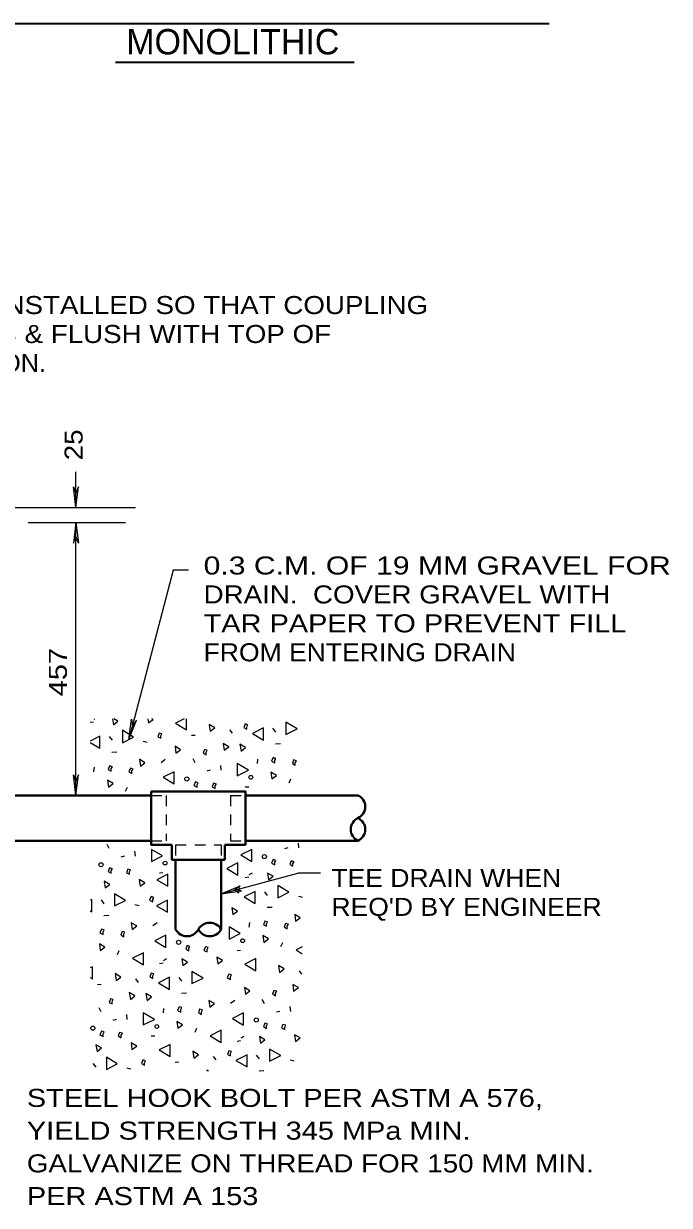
# Model space of a CAD drawing. Extents: x 312583 to 312854, y 144419 to 144597.
# Drawn here: x 312661.67 to 312688.9, y 144471.8 to 144521.63 of the extents above; entities that cross this region are included whole.
import ezdxf
from ezdxf.enums import TextEntityAlignment as Align

# ---------------------------------------------------------------- set-up
doc = ezdxf.new("R2010")
doc.units = 0
doc.header["$LTSCALE"] = 0.3
doc.linetypes.add('SHORT_DASHED', pattern=[2.7, 1.5, -1.2])
doc.layers.add('1', color=7, linetype='Continuous', lineweight=25)
doc.layers.add('2', color=7, linetype='Continuous', lineweight=13)

msp = doc.modelspace()

# ---------------------------------------------------------------- linework, layer by layer
at = {"layer": '1', "lineweight": 40}
for p, q in [((312658.9047, 144489.089), (312667.0467, 144489.089)), ((312671.0333, 144489.089), (312675.7713, 144489.089)), ((312658.9047, 144487.1723), (312667.0467, 144487.1723)), ((312667.9207, 144487.0113), (312667.9207, 144486.375)), ((312670.1593, 144487.0113), (312671.0333, 144487.0113)), ((312670.1593, 144487.0113), (312670.1593, 144486.375)), ((312671.0333, 144487.1723), (312675.7713, 144487.1723)), ((312667.9207, 144486.375), (312670.1593, 144486.375)), ((312668.0817, 144486.375), (312668.0817, 144483.4387)), ((312669.9983, 144486.375), (312669.9983, 144483.4387))]:
    msp.add_line(p, q, dxfattribs=at)
at = {"layer": '1', "linetype": 'SHORT_DASHED'}
for p, q in [((312667.0467, 144489.089), (312667.683, 144489.089)), ((312667.683, 144489.089), (312667.683, 144487.1723)), ((312670.397, 144489.089), (312670.397, 144487.1723)), ((312670.397, 144489.089), (312671.0333, 144489.089)), ((312667.0467, 144487.1723), (312667.683, 144487.1723)), ((312668.0817, 144487.0113), (312669.9983, 144487.0113)), ((312668.0817, 144487.0113), (312668.0817, 144486.375)), ((312669.9983, 144487.0113), (312669.9983, 144486.375)), ((312670.397, 144487.1723), (312671.0333, 144487.1723))]:
    msp.add_line(p, q, dxfattribs=at)
at = {"layer": '1', "lineweight": 40}
for points in [[(312667.0467, 144489.25), (312671.0333, 144489.25), (312671.0333, 144487.0113)], [(312667.0467, 144489.25), (312667.0467, 144487.0113), (312667.9207, 144487.0113)]]:
    msp.add_lwpolyline(points, dxfattribs=at)
for centre, radius, start, end in [((312675.5491, 144488.6118), 0.5279, 294.81419, 65.18581), ((312675.9922, 144487.6534), 0.5279, 114.81419, 245.18581), ((312675.5491, 144487.6534), 0.5279, 294.81419, 65.18581), ((312669.5192, 144483.175), 0.5466, 28.76662, 151.23338), ((312668.5608, 144483.7011), 0.5466, 208.76662, 331.23338), ((312669.5192, 144483.7011), 0.5466, 208.76662, 331.23338)]:
    msp.add_arc(centre, radius, start, end, dxfattribs=at)
at = {"layer": '2', "lineweight": 35}
for p, q in [((312657.2919, 144521.6292), (312683.8367, 144521.6292)), ((312665.5535, 144520.0115), (312675.611, 144520.0115))]:
    msp.add_line(p, q, dxfattribs=at)
at = {"layer": '2'}
for p, q in [((312663.8803, 144501.233), (312663.8803, 144502.7357)), ((312663.773, 144502.0993), (312663.8803, 144501.8233)), ((312663.8803, 144501.233), (312663.773, 144502.0993)), ((312663.9877, 144502.0993), (312663.8803, 144501.8233)), ((312663.8803, 144501.233), (312663.9877, 144502.0993)), ((312651.8743, 144501.233), (312666.395, 144501.233)), ((312661.8717, 144500.589), (312665.9657, 144500.589)), ((312663.8803, 144500.589), (312663.773, 144499.7227)), ((312663.8803, 144489.089), (312663.8803, 144500.589)), ((312663.8803, 144500.589), (312663.9877, 144499.7227)), ((312663.773, 144499.7227), (312663.8803, 144499.9987)), ((312663.9877, 144499.7227), (312663.8803, 144499.9987)), ((312664.486, 144492.171), (312664.624, 144492.194)), ((312664.647, 144492.3013), (312664.6777, 144492.3167)), ((312665.4213, 144492.3167), (312665.4597, 144492.0713)), ((312666.1113, 144491.4427), (312666.2263, 144492.309)), ((312666.1113, 144491.4427), (312666.4333, 144492.2553)), ((312666.2263, 144492.309), (312666.257, 144492.01)), ((312666.4333, 144492.2553), (312666.257, 144492.01)), ((312666.9087, 144492.3167), (312666.9317, 144492.148)), ((312668.5417, 144491.8567), (312668.5417, 144492.3167)), ((312665.2833, 144491.573), (312665.406, 144491.412)), ((312668.7563, 144491.6267), (312668.9097, 144491.6343)), ((312670.3587, 144491.8567), (312670.466, 144491.7187)), ((312672.168, 144491.918), (312672.2907, 144491.757)), ((312664.486, 144491.32), (312664.8923, 144491.0747)), ((312666.7093, 144491.3813), (312666.8857, 144491.3353)), ((312672.2907, 144491.2587), (312672.4977, 144491.274)), ((312665.3983, 144490.9137), (312665.6053, 144490.929)), ((312667.6447, 144490.607), (312667.4683, 144490.469)), ((312668.8023, 144490.6453), (312668.8867, 144490.4767)), ((312671.5317, 144490.4307), (312671.5547, 144490.6223)), ((312664.6393, 144490.0857), (312664.6623, 144490.2773)), ((312669.408, 144490.124), (312669.5537, 144490.1623)), ((312669.9677, 144490.354), (312669.9907, 144490.147)), ((312663.773, 144489.9553), (312663.8803, 144489.6793)), ((312663.8803, 144489.089), (312663.773, 144489.9553)), ((312663.9877, 144489.9553), (312663.8803, 144489.6793)), ((312663.8803, 144489.089), (312663.9877, 144489.9553)), ((312672.927, 144489.7713), (312672.8503, 144489.6027)), ((312666.0347, 144489.4263), (312665.958, 144489.2577)), ((312671.0103, 144489.4493), (312671.1637, 144489.457)), ((312665.1837, 144487.0267), (312665.268, 144486.858)), ((312667.913, 144486.812), (312667.936, 144487.0037)), ((312673.2413, 144487.0803), (312673.2643, 144486.8733)), ((312665.7893, 144486.5053), (312665.935, 144486.5437)), ((312666.349, 144486.7353), (312666.372, 144486.5283)), ((312672.6817, 144486.8503), (312672.8273, 144486.8887)), ((312667.3993, 144485.8307), (312667.545, 144485.8383)), ((312669.9983, 144484.9337), (312673.2337, 144485.8153)), ((312671.018, 144485.6237), (312671.1637, 144485.6543)), ((312671.1867, 144485.754), (312671.317, 144485.823)), ((312674.1843, 144485.8153), (312673.2337, 144485.8153)), ((312669.9983, 144484.9337), (312670.8033, 144485.271)), ((312669.9983, 144484.9337), (312670.8647, 144485.064)), ((312670.8033, 144485.271), (312670.5657, 144485.0947)), ((312670.8647, 144485.064), (312670.5657, 144485.0947)), ((312671.823, 144485.0257), (312671.9457, 144484.8647)), ((312664.9383, 144484.6807), (312665.061, 144484.5197)), ((312673.2567, 144484.834), (312673.4177, 144484.7957)), ((312664.486, 144484.2207), (312664.555, 144484.1823)), ((312665.0533, 144484.029), (312665.2603, 144484.0367)), ((312666.3643, 144484.489), (312666.5407, 144484.4507)), ((312671.9457, 144484.374), (312672.1527, 144484.3817)), ((312667.2997, 144483.7147), (312667.1233, 144483.5843)), ((312671.1867, 144483.5383), (312671.2097, 144483.73)), ((312665.6897, 144482.534), (312665.613, 144482.3653)), ((312670.673, 144482.557), (312670.8187, 144482.5647)), ((312672.582, 144482.879), (312672.5053, 144482.7103)), ((312667.3993, 144482.005), (312667.5527, 144482.0357)), ((312667.5757, 144482.1353), (312667.6983, 144482.212)), ((312673.2873, 144481.6983), (312673.3947, 144481.5527)), ((312664.486, 144481.407), (312664.578, 144481.3533)), ((312664.7927, 144481.1157), (312664.946, 144481.131)), ((312666.395, 144481.3533), (312666.5023, 144481.2077)), ((312668.212, 144481.407), (312668.3347, 144481.2537)), ((312668.327, 144480.7553), (312668.534, 144480.763)), ((312664.8387, 144480.142), (312664.923, 144479.9733)), ((312667.568, 144479.9273), (312667.591, 144480.1113)), ((312670.5733, 144480.441), (312670.397, 144480.3107)), ((312671.7233, 144480.487), (312671.8153, 144480.3183)), ((312672.8963, 144480.1957), (312672.9193, 144479.981)), ((312665.4443, 144479.613), (312665.59, 144479.659)), ((312666.004, 144479.8507), (312666.027, 144479.636)), ((312672.3367, 144479.958), (312672.4823, 144479.9963)), ((312668.9633, 144479.2603), (312668.8867, 144479.0917)), ((312667.0543, 144478.946), (312667.2, 144478.946)), ((312670.673, 144478.7313), (312670.8187, 144478.762)), ((312670.8417, 144478.8693), (312670.972, 144478.9383)), ((312669.6687, 144478.0797), (312669.776, 144477.934)), ((312671.478, 144478.1333), (312671.6007, 144477.98)), ((312664.5933, 144477.7883), (312664.716, 144477.635)), ((312666.027, 144477.5967), (312666.1957, 144477.5583)), ((312668.0663, 144477.842), (312668.2197, 144477.8573)), ((312672.9117, 144477.9417), (312673.0803, 144477.9033)), ((312671.6007, 144477.4817), (312671.8077, 144477.4893))]:
    msp.add_line(p, q, dxfattribs=at)
for points in [[(312668.626, 144498.588), (312667.9743, 144498.588), (312666.1113, 144491.4427)], [(312665.4597, 144492.0713), (312665.6513, 144492.217), (312665.4827, 144492.3167)], [(312666.9317, 144492.148), (312667.131, 144492.2937), (312667.085, 144492.3167)], [(312668.442, 144492.3167), (312668.074, 144492.1403), (312668.5417, 144491.8567)], [(312664.8923, 144491.0747), (312664.8923, 144491.5883), (312664.486, 144491.3813)], [(312664.555, 144484.1823), (312664.555, 144484.696), (312664.486, 144484.6653)], [(312673.4177, 144482.7027), (312673.157, 144482.5723), (312673.4177, 144482.4113)], [(312664.578, 144481.3533), (312664.578, 144481.867), (312664.486, 144481.821)], [(312669.4617, 144477.4663), (312669.4003, 144477.5047), (312669.408, 144477.4663)]]:
    msp.add_lwpolyline(points, dxfattribs=at)
for points in [[(312669.5383, 144491.7953), (312669.73, 144491.941), (312669.4923, 144492.079)], [(312671.087, 144491.987), (312671.133, 144492.0637), (312671.0103, 144492.102), (312670.9567, 144491.9487), (312671.087, 144491.8797)], [(312672.7353, 144492.1787), (312672.7353, 144491.6573), (312673.203, 144491.895)], [(312665.843, 144491.8337), (312665.843, 144491.3123), (312666.3107, 144491.55)], [(312667.4607, 144491.6037), (312667.5067, 144491.6803), (312667.3917, 144491.7187), (312667.3303, 144491.5653), (312667.4607, 144491.4963)], [(312671.7847, 144491.4197), (312671.7847, 144491.9333), (312671.317, 144491.7033)], [(312668.097, 144490.8677), (312668.2887, 144491.0133), (312668.0587, 144491.159)], [(312669.3697, 144490.9137), (312669.4157, 144490.9903), (312669.293, 144491.0287), (312669.2393, 144490.8753), (312669.3697, 144490.8063)], [(312670.1287, 144490.998), (312670.328, 144491.1437), (312670.0903, 144491.2817)], [(312670.8417, 144490.9597), (312671.0333, 144491.1053), (312670.7957, 144491.2433)], [(312666.5943, 144490.3233), (312666.786, 144490.469), (312666.556, 144490.6147)], [(312672.26, 144490.5687), (312672.306, 144490.6453), (312672.191, 144490.6837), (312672.1297, 144490.5303), (312672.26, 144490.4613)], [(312673.1263, 144490.469), (312673.1723, 144490.5457), (312673.0573, 144490.584), (312673.0037, 144490.4307), (312673.1263, 144490.3617)], [(312665.3677, 144490.2237), (312665.4137, 144490.3003), (312665.2987, 144490.3387), (312665.2373, 144490.1853), (312665.3677, 144490.1163)], [(312666.2417, 144490.124), (312666.2877, 144490.2007), (312666.1727, 144490.239), (312666.1113, 144490.0857), (312666.2417, 144490.0167)], [(312668.0203, 144489.572), (312668.0203, 144490.0857), (312667.5527, 144489.8557)], [(312670.6807, 144490.4307), (312670.6807, 144489.917), (312671.1483, 144490.1547)], [(312672.145, 144489.7867), (312672.3367, 144489.9323), (312672.099, 144490.0703)], [(312665.2527, 144489.4417), (312665.4443, 144489.5873), (312665.2143, 144489.7253)], [(312668.9863, 144489.5337), (312669.0323, 144489.618), (312668.9173, 144489.6563), (312668.856, 144489.503), (312668.9863, 144489.434)], [(312669.753, 144489.4877), (312669.799, 144489.5643), (312669.684, 144489.6027), (312669.6227, 144489.4493), (312669.753, 144489.3803)], [(312667.062, 144486.812), (312667.062, 144486.2983), (312667.5297, 144486.536)], [(312671.294, 144486.2983), (312671.294, 144486.812), (312670.8263, 144486.582)], [(312665.3677, 144485.9227), (312665.4137, 144485.9993), (312665.2987, 144486.0377), (312665.2373, 144485.8843), (312665.3677, 144485.8153)], [(312670.7113, 144485.731), (312670.7113, 144486.2447), (312670.2437, 144486.007)], [(312672.26, 144486.2677), (312672.306, 144486.3443), (312672.191, 144486.3827), (312672.1297, 144486.2293), (312672.26, 144486.1603)], [(312673.0267, 144486.214), (312673.0727, 144486.2907), (312672.95, 144486.329), (312672.8963, 144486.1757), (312673.0267, 144486.1067)], [(312666.1343, 144485.869), (312666.1803, 144485.9457), (312666.0653, 144485.984), (312666.004, 144485.8307), (312666.1343, 144485.7617)], [(312666.5867, 144485.2557), (312666.786, 144485.409), (312666.5483, 144485.547)], [(312667.752, 144485.2557), (312667.752, 144485.7693), (312667.2843, 144485.5317)], [(312671.9993, 144485.524), (312672.191, 144485.6773), (312671.961, 144485.8153)], [(312665.1147, 144485.1867), (312665.3063, 144485.3323), (312665.0687, 144485.4703)], [(312670.742, 144485.0947), (312670.788, 144485.179), (312670.673, 144485.2097), (312670.6117, 144485.064), (312670.742, 144484.9873)], [(312671.4397, 144484.5273), (312671.4397, 144485.041), (312670.972, 144484.811)], [(312672.3903, 144485.2863), (312672.3903, 144484.7727), (312672.858, 144485.0027)], [(312665.5057, 144484.9413), (312665.5057, 144484.4277), (312665.9657, 144484.6577)], [(312667.1157, 144484.7113), (312667.1617, 144484.788), (312667.0467, 144484.8263), (312666.9853, 144484.673), (312667.1157, 144484.604)], [(312667.7367, 144484.1593), (312667.7367, 144484.673), (312667.269, 144484.4353)], [(312670.4967, 144484.0673), (312670.6883, 144484.213), (312670.4507, 144484.351)], [(312673.1417, 144483.7837), (312673.3333, 144483.9293), (312673.1033, 144484.0673)], [(312666.2493, 144483.4387), (312666.441, 144483.5843), (312666.211, 144483.7223)], [(312670.3357, 144483.546), (312670.3357, 144483.0247), (312670.8033, 144483.2623)], [(312671.915, 144483.6763), (312671.961, 144483.7607), (312671.846, 144483.7913), (312671.7847, 144483.638), (312671.915, 144483.569)], [(312672.7813, 144483.5767), (312672.835, 144483.661), (312672.7123, 144483.6917), (312672.6587, 144483.5383), (312672.7813, 144483.4693)], [(312665.0227, 144483.3313), (312665.0687, 144483.4157), (312664.9537, 144483.4463), (312664.8923, 144483.293), (312665.0227, 144483.224)], [(312665.8967, 144483.2317), (312665.9427, 144483.316), (312665.8277, 144483.3467), (312665.7663, 144483.1933), (312665.8967, 144483.1243)], [(312667.6753, 144482.6797), (312667.6753, 144483.1933), (312667.2077, 144482.9633)], [(312671.8, 144482.8943), (312671.9917, 144483.04), (312671.754, 144483.178)], [(312664.9077, 144482.5493), (312665.0993, 144482.695), (312664.8693, 144482.833)], [(312668.6413, 144482.649), (312668.6873, 144482.7257), (312668.5723, 144482.764), (312668.511, 144482.6107), (312668.6413, 144482.5417)], [(312669.408, 144482.5953), (312669.454, 144482.6797), (312669.339, 144482.7103), (312669.2777, 144482.557), (312669.408, 144482.488)], [(312666.7323, 144481.9437), (312666.7323, 144482.4573), (312666.2647, 144482.2273)], [(312668.3807, 144481.913), (312668.58, 144482.0587), (312668.3423, 144482.1967)], [(312669.8603, 144481.9897), (312670.052, 144482.1353), (312669.822, 144482.2733)], [(312671.4703, 144481.6983), (312671.4703, 144482.212), (312671.0027, 144481.9743)], [(312665.5747, 144481.2843), (312665.7663, 144481.43), (312665.5363, 144481.5757)], [(312667.1233, 144481.476), (312667.1693, 144481.5603), (312667.0543, 144481.5987), (312666.993, 144481.4453), (312667.1233, 144481.3763)], [(312668.7717, 144481.6677), (312668.7717, 144481.154), (312669.2393, 144481.384)], [(312670.3893, 144481.4377), (312670.4353, 144481.522), (312670.3203, 144481.5527), (312670.259, 144481.3993), (312670.3893, 144481.3303)], [(312672.467, 144481.6293), (312672.6587, 144481.775), (312672.421, 144481.913)], [(312667.821, 144480.9087), (312667.821, 144481.43), (312667.3533, 144481.1923)], [(312673.0573, 144480.832), (312673.2567, 144480.9853), (312673.019, 144481.1233)], [(312665.406, 144480.4027), (312665.452, 144480.487), (312665.337, 144480.5177), (312665.2757, 144480.3643), (312665.406, 144480.2953)], [(312666.1727, 144480.487), (312666.3643, 144480.6403), (312666.1267, 144480.7783)], [(312666.878, 144480.4487), (312667.0697, 144480.5943), (312666.832, 144480.74)], [(312671.0257, 144480.7093), (312671.2173, 144480.855), (312670.9873, 144480.993)], [(312672.2907, 144480.7477), (312672.3443, 144480.832), (312672.2217, 144480.8627), (312672.168, 144480.7093), (312672.2907, 144480.6403)], [(312668.2963, 144480.0577), (312668.3423, 144480.142), (312668.2273, 144480.1727), (312668.166, 144480.027), (312668.2963, 144479.9503)], [(312669.1703, 144479.958), (312669.2163, 144480.0423), (312669.0937, 144480.073), (312669.04, 144479.9273), (312669.1703, 144479.8507)], [(312669.523, 144480.165), (312669.7147, 144480.3107), (312669.4847, 144480.4487)], [(312666.717, 144479.9273), (312666.717, 144479.4137), (312667.1847, 144479.6437)], [(312668.1813, 144479.2757), (312668.373, 144479.4213), (312668.1353, 144479.5593)], [(312670.949, 144479.406), (312670.949, 144479.9273), (312670.4813, 144479.6897)], [(312665.0227, 144479.0303), (312665.0687, 144479.1147), (312664.9537, 144479.1453), (312664.8923, 144478.992), (312665.0227, 144478.923)], [(312665.7893, 144478.9767), (312665.8353, 144479.061), (312665.7203, 144479.0917), (312665.659, 144478.946), (312665.7893, 144478.8693)], [(312670.006, 144478.67), (312670.006, 144479.1913), (312669.5383, 144478.9537)], [(312671.915, 144479.3753), (312671.961, 144479.4597), (312671.846, 144479.4903), (312671.7847, 144479.337), (312671.915, 144479.268)], [(312672.6817, 144479.3217), (312672.7277, 144479.406), (312672.605, 144479.4367), (312672.5513, 144479.2833), (312672.6817, 144479.2143)], [(312664.7697, 144478.2943), (312664.9613, 144478.44), (312664.7237, 144478.578)], [(312666.2417, 144478.371), (312666.441, 144478.5167), (312666.2033, 144478.6547)], [(312667.8517, 144478.0797), (312667.8517, 144478.5933), (312667.384, 144478.3557)], [(312671.6543, 144478.6393), (312671.846, 144478.785), (312671.616, 144478.923)], [(312673.134, 144478.716), (312673.3257, 144478.8617), (312673.0957, 144478.9997)], [(312665.1607, 144478.049), (312665.1607, 144477.5353), (312665.6207, 144477.773)], [(312668.8483, 144478.0107), (312669.04, 144478.1563), (312668.8023, 144478.302)], [(312670.397, 144478.21), (312670.443, 144478.2867), (312670.328, 144478.325), (312670.2667, 144478.1717), (312670.397, 144478.1027)], [(312671.0947, 144477.6427), (312671.0947, 144478.1563), (312670.627, 144477.9187)], [(312672.0453, 144478.394), (312672.0453, 144477.8803), (312672.513, 144478.118)], [(312666.7707, 144477.819), (312666.8167, 144477.9033), (312666.7017, 144477.934), (312666.6403, 144477.7883), (312666.7707, 144477.7117)]]:
    msp.add_lwpolyline(points, close=True, dxfattribs=at)
for centre, radius in [((312668.5533, 144489.7823), 0.0865), ((312671.253, 144489.8528), 0.0784), ((312671.8259, 144486.5097), 0.0865), ((312664.936, 144486.1651), 0.0865), ((312667.6358, 144486.2355), 0.0784), ((312670.9083, 144482.963), 0.0784), ((312668.2086, 144482.8925), 0.0865), ((312671.4812, 144479.6199), 0.0865), ((312664.5913, 144479.2752), 0.0865), ((312667.2911, 144479.3457), 0.0784)]:
    msp.add_circle(centre, radius, dxfattribs=at)

# ---------------------------------------------------------------- texts
msp.add_text('MONOLITHIC', height=1.07, dxfattribs=at).set_placement((312670.493, 144520.3305), align=Align.CENTER)
for s, width, p in [('CONDUIT SHALL BE INSTALLED SO THAT COUPLING', 1.15, (312648.984, 144509.3836)), ('IS EMBEDDED PLUMB & FLUSH WITH TOP OF', 1.15, (312648.984, 144508.1636)), ('CONCRETE FOUNDATION.', 1.05, (312648.984, 144506.9436)), ('0.3 C.M. OF 19 MM GRAVEL FOR', 1.25, (312669.2623, 144498.403)), ('DRAIN.  COVER GRAVEL WITH', 1.15, (312669.2623, 144497.183)), ('TAR PAPER TO PREVENT FILL', 1.2, (312669.2623, 144495.963)), ('FROM ENTERING DRAIN', 1.1, (312669.2623, 144494.743)), ('TEE DRAIN WHEN', 1.1, (312674.6488, 144485.2306)), ("REQ'D BY ENGINEER", 1.1, (312674.6488, 144484.0106)), ('STEEL HOOK BOLT PER ASTM A 576,', 1.2, (312661.8103, 144475.955)), ('YIELD STRENGTH 345 MPa MIN.', 1.2, (312661.8103, 144474.575)), ('GALVANIZE ON THREAD FOR 150 MM MIN.', 1.15, (312661.8103, 144473.195)), ('PER ASTM A 153', 1.2, (312661.8103, 144471.815))]:
    msp.add_text(s, height=0.76, dxfattribs=dict(at, width=width)).set_placement(p)
for s, width, p in [('25 ', 1.15, (312664.1601, 144503.2193)), ('457 ', 1.2, (312663.4979, 144493.2703))]:
    msp.add_text(s, height=0.76, rotation=90, dxfattribs=dict(at, width=width)).set_placement(p)

doc.saveas('drawing.dxf')
